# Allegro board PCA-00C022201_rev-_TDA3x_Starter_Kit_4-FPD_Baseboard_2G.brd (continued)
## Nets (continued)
DGND: C2.2 C3.2 C5.2 C6.2 C7.2 C20.2 C21.2 C23.2 C24.2 C25.1 C26.2 C27.2 C28.2 C29.1 C30.2 C31.2 C32.2 C33.1 C34.1 C35.2 C36.2 C37.2 C38.1 C39.1 C40.1 C41.2 C42.2 C43.2 C44.1 C45.1 C46.2 C47.2 C48.2 C49.1 C50.1 C51.1 C52.2 C53.2 C54.2 C55.1 C56.1 C57.2 C58.2 C59.2 C60.1 C63.2 C65.1 C66.2 C67.1 C68.2 C69.1 C70.2 C71.1 C72.2 C79.1 C80.2 C81.1 C82.2 C83.1 C84.2 C85.1 C86.2 C107.2 C108.2 C109.2 C110.2 C111.2 C123.2 C124.2 C125.2 C126.2 C127.2 C128.2 C129.2 C130.2 C131.2 C132.2 C135.2 C136.2 C137.2 C140.2 C141.2 C142.2 C143.2 C144.2 C145.2 C146.2 C150.2 C151.2 C152.2 C153.2 C155.1 C156.2 C157.2 C158.2 C159.2 C160.2 C161.2 C162.2 C163.2 C164.2 C165.2 C166.2 C167.2 C168.2 C175.2 C176.2 C177.2 C178.2 C179.2 C180.2 C181.2 C182.2 C183.2 C184.2 C186.2 C187.2 C191.2 C192.2 C193.2 C194.2 C207.2 C208.2 C213.2 C217.2 C218.2 C220.2 C221.2 C222.2 C223.2 C224.2 C229.2 C230.2 C231.2 C232.2 C235.2 C236.2 C237.2 C238.2 C239.2 C240.2 C241.2 C242.2 C243.2 C246.2 C247.2 C248.2 C250.2 C251.2 C252.2 C253.2 C254.2 C255.2 C256.2 C257.2 C258.2 C259.2 C260.2 C261.2 C262.2 C263.2 C264.2 C265.2 C266.2 C267.2 D1.A1 D1.A2 D8.1 D9.2 D21.A D23.C(CATHODE) J6.1 J6.2 J6.3 J6.4 J7.1 J7.2 J7.3 J7.4 J8.1 J8.2 J8.3 J8.4 J9.1 J9.2 J9.3 J9.4 J13.16 J13.57 J13.58 J13.61 J13.62 J13.63 J13.64(GND4) J14.93 J14.94 J14.99 J14.100 J14.105 J14.106 J14.111 J14.181 J14.182 J14.183 J14.184 J14.185 J14.186 J14.187 J14.188 J14.189(GND9) J14.190 J14.191 J14.192 J19.1 J19.4 J19.7 J19.10 J19.13 J19.20 J19.21 J19.22 J19.23 J21.6(VSS) J21.10 J25.2 J25.3 J26.1 J26.4 J26.7 J26.10 J26.13 J26.20 J26.21 J26.22 J26.23 J27.15 J27.16 J28.5 J28.7 J29.3 L41.1 Q7.2(S) Q8.2(S) R13.2 R14.2 R28.2 R31.2 R35.2 R53.2 R61.2 R67.1 R68.1 R69.1 R70.1 R75.1 R76.1 R77.1 R78.1 R111.2 R112.1 R117.2 R130.2 R135.2 R166.2 R181.2 R182.2 R183.2 R186.2 R187.2 R189.2 R191.2 R193.2 R195.2 R199.2 R201.2 R203.2 R207.2 R223.2 R224.2 R225.2 R226.2 R227.2 R228.2 R229.2 R230.2 R234.2 R238.2 R240.2 R247.2 R248.2 R269.2 R290.2 R294.2 R295.2 R296.2 R297.2 R298.2 R302.2 R303.2 R304.2 R306.1 R307.1 R315.2 R323.2 R324.2 R327.2 SW1.1 SW2.5(B4) TP2.1 TP70.1 TP72.1 U1.8 U1.11 U4.1 U4.7 U5.3 U5.6 U5.14 U5.15 U5.17 U6.65(VSS/PAD) U7.2 U9.49 U10.2 U13.1 U13.4 U13.9 U14.2 U16.16 U16.17 U16.20 U16.26 U16.32 U16.34 U16.48 U16.56 U16.64 U16.65 U20.3 U20.5 U20.8 U20.11 U20.14 U20.25(TMDS_GND.8) U20.28 U20.31 U20.34 U20.36 U21.5 U21.9 U22.12 U28.2 U38.2 U38.8 U38.9 U38.14 U38.15 U38.17 U41.2 U42.2 U43.3 U43.5 U43.8(TMDS_GND#8) U43.11 U43.14 U43.25 U43.28 U43.31 U43.34 U43.36 U44.65 U45.4 U46.8 U46.10 U46.11 U46.13 U46.14 U47.3 U47.12 U47.21 U48.10 U48.11 U48.12 U48.21 U49.4
DVDD_HDMI_IN: C239.1 C240.1 C241.1 C242.1 C243.1 L49.2 U44.24 U44.40 U44.52 U44.60
PVDD_HDMI_IN: C250.1 C251.1 L51.2 U44.57
VDD1P1: C127.1 C128.1 C129.1 C130.1 C143.1 C146.1 C255.1 C256.1 C257.1 C260.1 L37.2 U9.6 U9.24 U9.31 U9.42
VDD18_P: C47.1 C48.1 C49.2 C50.2 C51.2 L8.2 U6.1 U6.2 U6.47 U6.48
VDD18A: C27.1 C28.1 C29.2 L4.2 U6.32
VDD_1V1: C23.1 C24.1 C30.1 C41.1 C52.1 L3.2 L5.1 L7.1 L9.1 L37.1 R33.1 R34.2 TP13.1 U5.16(VOS)
VDD_1V1_EN: R172.2 TP32.1 U5.13
VDD_1V8: C184.1 J14.8 J14.10 R51.1 R58.1 TP74.1 U21.1 U21.2
VDD_2V5: C125.1 C126.1 L36.2 L38.1 R118.2 R120.1 TP17.1 U13.6(VOS)
VDD_2V5_EN: R309.2 TP33.1 U13.3
VDD_3V3: C57.1 C110.1 C160.1 C161.1 C162.1 C165.1 C167.1 C168.1 C180.1 C181.1 C182.1 C186.1 C187.1 C207.1 C217.1 C218.1 C263.1 C265.1 J13.1 J13.12 J14.7 J14.9 J21.4 J27.1 L10.1 L40.1 L42.1 L43.2 L47.1 L48.1 R107.1 R108.1 R131.2 R132.1 R133.1 R136.1 R137.1 R138.1 R152.1 R153.1 R154.1 R155.1 R156.1 R157.1 R158.1 R172.1 R184.1 R185.1 R188.1 R190.1 R192.1 R194.1 R196.1 R197.1 R200.1 R202.1 R204.1 R205.1 R206.1 R222.2 R237.1 R259.1 R260.1 R308.1 R309.1 R310.1 R312.1 R316.1 R317.1 R318.1 TP83.1 U10.5(VIO) U16.1 U16.12 U16.33 U22.24(VCC) U28.5(V+) U38.1 U38.3 U41.5(VCC) U42.5(VCC) U46.16(VCC) U48.20(VCC)
VDD_5V0: C20.1 C109.1 C175.1 C222.1 R276.1 R277.1 R313.1 R314.1 TP12.1 U4.2(VOUT) U4.3 U10.3 U20.1 U43.1
VDD_5V0_EN: R310.2 TP34.1 U4.4
VDD_BB_1V8: C26.1 C35.1 C46.1 C140.1 L4.1 L6.1 L8.1 L49.1 L50.1 L51.1 TP75.1 U14.1 U14.4(VCC) U21.7(VOUT.2) U21.8
VDD_BB_3V3: C3.1 C21.1 C124.1 C156.1 C178.1 C183.1 J14.1 J14.3 J14.5 L1.2 L2.1 R8.1 R10.1 TP1.1 U4.6 U5.10 U5.11 U5.12 U13.2 U21.4
VDD_HDMI_5V0: C166.1 J19.18 U20.38
VDD_SW_FPD: C67.2 C68.1 C71.2 C72.1 C81.2 C82.1 C85.2 C86.1 L11.2 L12.2 L21.2 L22.2 R250.1 TP11.1 U3.5 U3.6 U3.7
VDD_USB_3V3: C193.1 C194.1 C208.1 R301.1 U38.16(VCCB) U47.6
VDD_USB_5V0: C191.1 C192.1 C213.1 J23.1 U47.7 U47.8 U49.1(VCC)
VDD_VIN: C2.1 C266.1 C267.1 J25.1 R249.1 TP27.1 U1.2(VIN) U3.8 U3.9(VS#9) U3.10
VDDA1P8: U9.13 U9.48
VDDA2P5: C131.1 C132.1 C142.1 C145.1 C254.1 C262.1 L38.2 U9.3 U9.9
VDDCSI: C42.1 C43.1 C44.2 C45.2 L7.2 U6.21 U6.33
VDDFPD: C53.1 C54.1 C55.2 C56.2 L9.2 U6.52 U6.61
VDDFPD18: C36.1 C37.1 C38.2 C39.2 C40.2 L6.2 U6.49 U6.55 U6.58 U6.64
VDDIO_960: C58.1 C59.1 C60.2 C123.1 L10.2 R42.1 R59.1 R60.1 R328.1 R329.1 U6.16 U7.4(VCC)
VDDIO_HDMI_IN: C229.1 C230.1 C231.1 C232.1 C264.1 L47.2 R278.2 R280.1 R281.1 R282.1 R283.1 R286.2 R287.2 R305.1 U44.23 U44.34 U44.44 U45.8
VDDIO_PHY: C135.1 C136.1 C137.1 C141.1 C144.1 C258.1 C259.1 C261.1 L40.2 R121.1 R125.1 R311.1 U9.19 U9.30 U9.41
VDDL: C31.1 C32.1 C33.2 C34.2 L5.2 U6.13 U6.44
VIN1A_CLK0: J14.73 R271.1 TP84.1
VIN1A_D0: J14.74 RN1.4
VIN1A_D1: J14.71 RN1.3
VIN1A_D2: J14.69 RN1.2
VIN1A_D3: J14.72 RN1.1
VIN1A_D4: J14.70 RN2.4
VIN1A_D5: J14.68 RN2.3
VIN1A_D6: J14.67 RN2.2
VIN1A_D7: J14.65 RN2.1
VIN1A_D8: J14.66 RN3.4
VIN1A_D9: J14.63 RN3.3
VIN1A_D10: J14.61 RN3.2
VIN1A_D11: J14.59 RN3.1
VIN1A_D12: J14.57 RN4.4
VIN1A_D13: J14.62 RN4.3
VIN1A_D14: J14.64 RN4.2
VIN1A_D15: J14.55 RN4.1
VIN1A_DE0: J14.75 R274.1 TP86.1
VIN1A_HSYNC0: J14.78 R272.1 TP85.1
VIN1A_VSYNC0: J14.76 R273.1 TP87.1
ADC_IN2: D21.C(CATHODE) J14.20 R26.1 R231.1
ADC_IN4: J14.15 R251.2
ADC_IN5: J14.13 R252.2
ADV7611_RSTN: R290.1 U22.10 U44.56
ADV7611_SCL: R288.1 R291.2 U44.53
ADV7611_SDA: R289.1 R292.2 U44.54
BB_3V3_PG: J14.130 R8.2 TP28.1 TP56.1 U1.10
BOARD_ID0: R185.2 R186.1 U22.13
BOARD_ID1: R187.1 R188.2 U22.14
BOARD_ID2: R189.1 R190.2 U22.15
BOARD_ID3: R191.1 R192.2 U22.16
BUF_INPUT0: J28.2 R265.1
BUF_INPUT1: J28.4 R266.1
BUF_OUT0: J28.6 R267.1
BUF_OUT1: J28.8 R268.1
CSI2_0_DX0: J14.104 U6.23
CSI2_0_DX1: J14.109 U6.25
CSI2_0_DX2: J14.103 U6.27
CSI2_0_DX3: J14.98 U6.29
CSI2_0_DX4: J14.97 U6.31
CSI2_0_DY0: J14.102 U6.22
CSI2_0_DY1: J14.107 U6.24
CSI2_0_DY2: J14.101 U6.26
CSI2_0_DY3: J14.96 U6.28
CSI2_0_DY4: J14.95 U6.30
CVDD_HDMI_IN: C246.1 C247.1 C248.1 L50.2 U44.2 U44.14
DCAN1_H: C107.1 D9.1 J28.1 R92.1 U10.7
DCAN1_L: C108.1 D8.2 J28.3 R93.1 U10.6
DCAN1_RX: J14.113 R91.1
DCAN1_STSB: R89.1 U22.11
DCAN1_TX: J14.115 R90.1
DCAN2_RX: J14.110 J27.14
DCAN2_TX: J14.108 J27.12
EDID_EEPROM_WP: R305.2 SW2.4 U45.7(WP)
EDID_SCL: TP88.1 U45.6 U46.4
EDID_SDA: TP89.1 U45.5 U46.7
EDID_SEL: R307.2 SW2.3 U46.1
EMU0: J13.19 J14.175
EMU1: J13.21 J14.173
EMU_RSTN: J13.6 J14.172 R108.2
ENET_CLKIN: R233.2 U9.15
FPD_960_EN: R270.1 U22.17
FPD_960_GPIO4: TP22.1 U6.17 U22.4
FPD_960_GPIO5: TP24.1 U6.18 U22.5
FPD_960_GPIO6: TP23.1 U6.19 U22.6
FPD_960_GPIO7: TP25.1 U6.20 U22.7
FPD_960_IDX: C63.1 R51.2 R53.1 U6.46
FPD_960_MODE: R58.2 R61.1 U6.45
FPD_960_PDB: R269.1 R270.2 U6.3
FPD_960_REFCLK: R45.1 U7.3
FPD_960_SCL: R38.1 R39.1 U6.12
FPD_960_SCL2: J29.1 R43.1 R44.1 R328.2 U6.8
FPD_960_SDA: R36.1 R37.1 U6.11
FPD_960_SDA2: J29.2 R40.1 R41.1 R329.2 U6.7
FPD_960_TESTEN: R60.2 SW1.2(B1) U6.4
GPIO2_0: J14.77 R231.2
GPIO2_19: J14.56 R180.1 R234.1 TP40.1
GPIO3_19: J14.89 U41.6
GPIO3_20: J14.81 U41.4
GPIO3_21: J14.85 R297.1 U42.1
GPIO3_22: J14.87 R298.1 U42.3
GPIO3_23: J14.83 R24.1
GPIO3_24: J14.79 R25.1
GPIO4_5: J14.161 TP18.1 U6.9
GPIO4_6: J14.163 TP19.1 U6.10
GPIO4_7: J14.165 TP20.1 U6.14
GPIO4_8: J14.167 TP21.1 U6.15
GPIO4_21: J14.58 R287.1 U44.55
GPIO4_22: J14.60 R197.2 U22.1
GPMC_AD3: J14.144 SW2.2
GPMC_AD4: J14.145 SW2.1
GPMC_AD10: J14.151 R202.2
GPMC_AD11: J14.152 R201.1
GPMC_AD12: J14.153 R200.2
GPMC_CS1: J14.125 TP58.1
GPMC_CS2: J14.127 TP61.1
GPMC_CS3: J14.133 TP63.1
GPMC_CS4: J14.131 TP60.1
GPMC_CS5: J14.129 TP62.1
GPMC_CS6: J14.123 TP59.1
HDMI_IN_5V0: C220.1 J26.18 R275.1 R285.2
HDMI_IN_CEC: R283.2 U43.16 U44.61
HDMI_IN_CLK: R271.2 U44.25
HDMI_IN_CLKN: J26.12 U43.15 U43.24 U44.3
HDMI_IN_CLKP: J26.11 U43.13 U43.26 U44.4
HDMI_IN_D0: RN1.5 U44.43
HDMI_IN_D0N: J26.9 U43.12 U43.27 U44.6
HDMI_IN_D0P: J26.8 U43.10 U43.29 U44.7
HDMI_IN_D1: RN1.6 U44.42
HDMI_IN_D1N: J26.6 U43.9 U43.30 U44.9
HDMI_IN_D1P: J26.5 U43.7 U43.32 U44.10
HDMI_IN_D2: RN1.7 U44.41
HDMI_IN_D2N: J26.3 U43.6 U43.33 U44.12
HDMI_IN_D2P: J26.2 U43.4 U43.35 U44.13
HDMI_IN_D3: RN1.8 U44.39
HDMI_IN_D4: RN2.5 U44.38
HDMI_IN_D5: RN2.6 U44.37
HDMI_IN_D6: RN2.7 U44.36
HDMI_IN_D7: RN2.8 U44.35
HDMI_IN_D8: RN3.5 U44.33
HDMI_IN_D9: RN3.6 U44.32
HDMI_IN_D10: RN3.7 U44.31
HDMI_IN_D11: RN3.8 U44.30
HDMI_IN_D12: RN4.5 U44.29
HDMI_IN_D13: RN4.6 U44.28
HDMI_IN_D14: RN4.7 U44.27
HDMI_IN_D15: RN4.8 U44.26
HDMI_IN_DDC_SCL: R281.2 U43.17 U44.62 U46.2
HDMI_IN_DDC_SDA: R282.2 U43.18 U44.63 U46.5
HDMI_IN_DE: R274.2 U44.45
HDMI_IN_HPDET: R286.1 U43.19 U44.1
HDMI_IN_HS: R272.2 U44.46
HDMI_IN_VS: R273.2 U44.47
HDMI_OUT_HPD: R316.2 U20.19 U22.19
HDMI_OUT_SCL: R318.2 R319.2 R320.2 U20.17
HDMI_OUT_SDA: R317.2 R321.2 R322.2 U20.18
I2C1_SCL: J14.156 J27.7 R38.2 R43.2 R291.1 R319.1
I2C1_SDA: J14.154 J27.9 R36.2 R40.2 R292.1 R321.1
I2C2_SCL: J14.120 J27.11 R39.2 R44.2 R288.2 R320.1 U22.22 U28.1 U46.3
I2C2_SDA: J14.122 J27.13 R37.2 R41.2 R289.2 R322.1 U22.23 U28.6 U46.6
LPTX_C_N: C62.2 R46.2 TP6.1
LPTX_C_P: C61.2 R46.1 TP5.1
LPTXN: C62.1 U6.57
LPTXP: C61.1 U6.56
MDIO_D: J14.91 R125.2 R311.2 TP47.1 U9.17
MDIO_MCLK: J14.92 TP48.1 U9.16
MMC_CLK: J21.5 R148.2 R155.2
MMC_CMD: J21.3 R147.2 R154.2
MMC_DAT0: J21.7 R149.2 R156.2
MMC_DAT1: J21.8 R150.2 R157.2
MMC_DAT2: J21.1 R145.2 R152.2
MMC_DAT3: J21.2 R146.2 R153.2
NTRST: J13.9 R107.2 R110.1
PB_RESETN: J14.171 TP77.1
PG_1V1: R34.1 TP69.1 U5.4
PHY_LED0: D12.A U9.47
PHY_LED1: J24.15 U9.46
PHY_LED2: J24.14 U9.45
PMIC_REGEN_3V3: J14.26 TP80.1
PWRON: J14.24 TP79.1
QSPI1_RTCLK: J14.121 TP57.1
RGMII0_RXC: J14.90 R148.1
RGMII0_RXCTL: J14.82 R147.1
RGMII0_RXD0: J14.86 R146.1
RGMII0_RXD1: J14.80 R145.1
RGMII0_RXD2: J14.84 R150.1
RGMII0_RXD3: J14.88 R149.1
RGMII1_RXC: J14.155 R199.1 U48.2
RGMII1_RXCTL: J14.132 U48.7
RGMII1_RXD0: J14.143 R205.2 U48.3
RGMII1_RXD1: J14.142 R206.2 U48.4
RGMII1_RXD2: J14.141 R207.1 U48.5
RGMII1_RXD3: J14.140 U48.6
RGMII1_TXC: J14.135 U9.29
RGMII1_TXCTL: J14.138 U9.37
RGMII1_TXD0: J14.134 U9.28
RGMII1_TXD1: J14.136 U9.27
RGMII1_TXD2: J14.137 U9.26
RGMII1_TXD3: J14.139 U9.25
RIN0_C_N: C75.1 C77.2 L19.1 L19.2 R67.2
RIN0_C_P: C73.1 J6.5 L17.2 L19.3 L19.4
RIN0_N: C75.2 U6.51
RIN0_P: C73.2 U6.50
RIN1_C_N: C76.1 C78.2 L20.1 L20.2 R68.2
RIN1_C_P: C74.1 J7.5 L18.2 L20.3 L20.4
RIN1_N: C76.2 U6.54
RIN1_P: C74.2 U6.53
RIN2_C_N: C89.1 C91.2 L29.1 L29.2 R75.2
RIN2_C_P: C87.1 J8.5 L27.2 L29.3 L29.4
RIN2_N: C89.2 U6.60
RIN2_P: C87.2 U6.59
RIN3_C_N: C90.1 C92.2 L30.1 L30.2 R76.2
RIN3_C_P: C88.1 J9.5 L28.2 L30.3 L30.4
RIN3_N: C90.2 U6.63
RIN3_P: C88.2 U6.62
RSTOUTN: J14.170 TP78.1 U22.3
RTCK: J13.7 J14.179
RX_CLK: R179.2 U9.32
RX_CTRL: R174.2 U9.38
RX_D0: RN5.8 U9.33
RX_D1: RN5.7 U9.34
RX_D2: RN5.6 U9.35
RX_D3: RN5.5 U9.36
SD_DETECT: R151.2 R158.2 U22.18
SPI1_CS1/SPI3_CS1: J14.162 J27.10
SW_RX_CLK: R179.1 U48.18
SW_RX_CTRL: R174.1 U48.13
SW_RX_D0: RN5.1 U48.17
SW_RX_D1: RN5.2 U48.16
SW_RX_D2: RN5.3 U48.15
SW_RX_D3: RN5.4 U48.14
TCLK: J13.3 J14.180
TD_A_N: J24.10 U9.2
TD_A_P: J24.11 U9.1
TD_B_N: J24.5 U9.5
TD_B_P: J24.4 U9.4
TD_C_N: J24.2 U9.8
TD_C_P: J24.3 U9.7
TD_D_N: J24.9 U9.11
TD_D_P: J24.8 U9.10
TDI: J13.5 J14.174
TDO: J13.4 J14.176
TFP410_DKEN: R137.2 U16.35
TFP410_HTPLG: R136.2 U16.9
TFP410_MSEN: R138.2 U16.11
TFP410_PDN: R134.2 U22.20
TFP410_TFADJ: R139.1 U16.19
TMS: J13.2 J14.178
TRSTN: J14.177 R109.2 R110.2
TRSTPD: J13.8 R109.1 R111.1
TVDD: C157.1 C158.1 C163.1 L42.2 R139.2 U16.23 U16.29
TVDD_HDMI_IN: C235.1 C236.1 C237.1 C238.1 L48.2 U44.5 U44.8 U44.11
TXC_N: J19.12 U16.21 U20.15 U20.24
TXC_P: J19.11 U16.22 U20.13 U20.26
TXD0_N: J19.9 U16.24 U20.12 U20.27
TXD0_P: J19.8 U16.25 U20.10 U20.29
TXD1_N: J19.6 U16.27 U20.9 U20.30
TXD1_P: J19.5 U16.28 U20.7 U20.32
TXD2_N: J19.3 U16.30 U20.6 U20.33
TXD2_P: J19.2 U16.31 U20.4 U20.35
UART1_RXD/DCAN2_TX: J14.117 J27.3
UART1_TXD/DCAN2_RX: J14.119 J27.5
UART2_CTSN: J14.114 J27.6 Q7.1 R324.1
UART2_RTSN: J14.112 J27.8 Q8.1 R323.1
UART2_RXD: J14.118 J27.4
UART2_TXD: J14.116 J27.2
UART3_CTSN: J14.164 R104.2
UART3_RTSN: J14.166 R101.2
UART3_RXD_BOOT: J14.158 R105.2
UART3_TXD_BOOT: J14.160 R102.2
USB_CTS: R299.1 U47.15
USB_DM: J23.2 U47.5 U49.2 U49.5
USB_DP: J23.3 U47.4 U49.3
USB_RTS: R300.1 U47.16
USB_RXD: U38.11 U47.17
USB_TXD: U38.13 U47.18
VOUT1_CLK: J14.51 U16.57
VOUT1_D0: J14.43 U16.63
VOUT1_D1: J14.41 U16.62
VOUT1_D2: J14.39 U16.61
VOUT1_D3: J14.37 U16.60
VOUT1_D4: J14.54 U16.59
VOUT1_D5: J14.52 U16.58
VOUT1_D6: J13.13 J14.35 U16.55
VOUT1_D7: J13.17 J14.50 U16.54
VOUT1_D8: J13.23 J14.48 U16.53
VOUT1_D9: J13.25 J14.46 U16.52
VOUT1_D10: J13.27 J14.44 U16.51
VOUT1_D11: J13.29 J14.42 U16.50
VOUT1_D12: J13.31 J14.40 U16.47
VOUT1_D13: J13.33 J14.38 U16.46
VOUT1_D14: J13.35 J14.36 U16.45
VOUT1_D15: J13.37 J14.34 U16.44
VOUT1_D16: J13.39 J14.31 U16.43
VOUT1_D17: J13.41 J14.32 U16.42
VOUT1_D18: J13.43 J14.33 U16.41
VOUT1_D19: J13.45 J14.30 U16.40
VOUT1_D20: J13.47 J14.29 U16.39
VOUT1_D21: J13.49 J14.27 U16.38
VOUT1_D22: J13.51 J14.28 U16.37
VOUT1_D23: J13.53 J14.25 U16.36
VOUT1_DE: J14.45 U16.2
VOUT1_FLD: J14.53 R237.2 U48.19
VOUT1_HSYNC: J14.49 U16.4
VOUT1_VSYNC: J14.47 U16.5(VSYNC)
WARM_RESETN: J14.169 TP76.1
XREF_CLK/TIMER3: J14.124 R121.2 TP14.1 U9.44
N16778655: C1.1 U1.1
N16778658: C1.2 D1.C(CATHODE) L1.1 U1.9
N16779093: C6.1 R12.1 U1.7
N16779143: R13.1 U1.5
N16779358: C5.1 U1.4
N16782242: L2.2 U4.5
N16784059: R26.2 R28.1 U3.14
N16784098: R24.2 U3.3
N16784610: R30.1 U3.13
N16784791: D23.A1 D23.A2 R30.2 R31.1 U3.2 U3.15
N16787891: L3.1 U5.1 U5.2
N16788418: C25.2 U5.9
N16788506: C22.2 U5.7
N16788509: C22.1 U5.8
N16799359: C77.1 R69.2
N16799482: L13.1 LR5.1 R63.1
N16799508: L13.2 L14.1 R63.2 R64.1
N16799567: C65.2 C66.1 L11.1 L14.2 R64.2
N16800770: C78.1 R70.2
N16800832: L15.1 LR6.1 R65.1
N16800854: L15.2 L16.1 R65.2 R66.1
N16800876: C69.2 C70.1 L12.1 L16.2 R66.2
N16801557: C91.1 R77.2
N16801619: L23.1 LR7.1 R71.1
N16801641: L23.2 L24.1 R71.2 R72.1
N16801663: C79.2 C80.1 L21.1 L24.2 R72.2
N16802378: C92.1 R78.2
N16802440: L25.1 LR8.1 R73.1
N16802462: L25.2 L26.1 R73.2 R74.1
N16802472: C83.2 C84.1 L22.1 L26.2 R74.2
N16805253: R59.2 U7.1
N16808896: R45.2 U6.5
N16808937: R42.2 TP4.1 U6.6
N16828608: R90.2 U10.1
N16828611: R91.2 U10.4
N16829078: C111.1 R92.2 R93.2
N16848362: J13.15 R112.2
N16871816: R117.1 U9.12
N16872761: L36.1 U13.7
N16872796: R118.1 U13.8
N16872856: R119.1 R120.2 U13.5
N16877045: R233.1 U14.3
N16921638: R25.2 U3.12
N16945191: C150.1 J24.12
N16950158: C151.1 J24.6
N16950163: C152.1 J24.1
N16950168: C153.1 J24.7
N16959967: R131.1 U16.3
N16959972: R130.1 R134.1 U16.10
N16959998: R132.2 U16.15
N16960003: R133.2 U16.14
N16960049: R135.1 U16.13
N16962010: C159.1 C164.1 L43.1 U16.18
N16974466: J21.9 R151.1
N16989017: R89.2 R166.1 U10.8
N17023402: R10.2 R14.1 U1.6
N17041661: R180.2 U9.43
N17043205: D12.C(CATHODE) R181.1
N17043208: J24.13 R182.1
N17043211: J24.16 R183.1
N17061008: R184.2 TP44.1 U21.3
N17061570: C179.1 U21.6
N17062531: R193.1 R194.2 U22.2
N17062635: R195.1 R196.2 U22.21
N17083264: R222.1 U28.4
N17084179: J14.11 TP50.1
N17084298: J14.23 TP51.1
N17084336: J14.12 TP52.1
N17084566: J14.22 TP53.1
N17086992: J14.126 TP54.1
N17087001: J14.128 TP55.1
N17088234: MH1.1 R223.1
N17088237: MH2.1 R224.1
N17088240: MH3.1 R225.1
N17088243: MH4.1 R226.1
N17088661: MH5.1 R227.1
N17088663: MH6.1 R228.1
N17088675: MH7.1 R229.1
N17088677: MH8.1 R230.1
N17350751: J23.5 J23.6 J23.7 J23.8 J23.9(SHIELD4) R240.1
N17371221: R102.1 U38.6
N17371356: R105.1 U38.4
N17389734: R247.1 R249.2 R251.1
N17389895: R248.1 R250.2 R252.1
N17515572: D18.C(CATHODE) Q7.3
N17515594: D18.A R259.2
N17515834: D17.C(CATHODE) Q8.3
N17515881: D17.A R260.2
N17688900: R204.2 SW2.7
N17688914: R203.1 SW2.8
N17750408: L17.1 LR1.2
N17835449: C155.2 J24.17 J24.18(SHLD2) L41.2
N17854884: C177.1 R312.2 U20.2
N17856030: C176.1 U20.37
N17857226: J19.15 R313.2 U20.22
N17857229: J19.16(SDA) R314.2 U20.21
N17857232: J19.19 R315.1 U20.20
N17858343: J26.14 R278.1 U43.23
N17858344: J26.15 R277.2 U43.22
N17858345: J26.16(SDA) R276.2 U43.21
N17858346: J26.19 R275.2 R294.1 U43.20
N17880680: C221.1 U43.37
N17880809: C223.1 R280.2 U43.2
N17882114: C224.1 R285.1 U44.64
N17895085: C252.1 R293.1 U44.58(XTALP) Y2.1
N17895092: C253.1 R293.2 U44.59 Y2.2
N17937761: R238.1 U48.1
N17941586: R265.2 R296.1 U41.1
N17941618: R266.2 R295.1 U41.3
N17941727: R267.2 U42.6
N17941759: R268.2 U42.4
N17942689: R299.2 U38.10
N17942746: R300.2 U38.12
N17942762: R104.1 U38.5
N17942771: R101.1 U38.7
N17945605: R301.2 U47.9
N17947242: L27.1 LR3.2
N17947474: L28.1 LR4.2
N17947670: L18.1 LR2.2
N17947891: LR1.1 LR5.2
N17947954: LR2.1 LR6.2
N17948346: LR4.1 LR8.2
N17948389: LR3.1 LR7.2
N17949147: R304.1 U45.1
N17949152: R303.1 U45.2
N17949167: R302.1 U45.3
N17955828: R306.2 U46.15
N17957422: R308.2 SW2.6
N18040269: R12.2 R325.1
N18040280: C7.1 R325.2
N18040766: R35.1 R326.2 U5.5
N18041733: R119.2 R327.1
N167880061: R33.2 R326.1

Pads without a net: D8 3; D9 3; J13 10 11 14 18 20 22 24 26 28 30 32 34 36 38 40 42 44 46 48 50 52 54 55 56 59 60; J14 2 4 6 14 16 17 18 19 21 146 147 148 149 150 157 159 168; J19 14 17; J23 4; J26 17; U1 3; U3 1 4 11; U6 34 35 36 37 38 39 40 41 42 43; U9 14 18 20 21 22 23 39 40; U16 6 7 8 49; U20 16 23; U22 8 9; U28 3; U43 38; U44 15 16 17 18 19 20 21 22 48 49 50 51; U46 9 12; U47 1 2 10 11 13 14 19 20; U48 8 9

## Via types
v1: diameter 0.457, hole 0.203, TOP to BOTTOM, 903 vias
v2: diameter 0.559, hole 0.305, TOP to BOTTOM, 201 vias

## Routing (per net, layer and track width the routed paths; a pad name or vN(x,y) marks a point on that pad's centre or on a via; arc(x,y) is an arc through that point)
DGND: length 1055.8
  TOP w0.203: v1(94.52,4.67) 94.81,4.96 U5.3 ; U45.4 v1(67.99,64.23) ; U48.12 v1(83.54,20.83) ; U48.11 v1(84.84,19.04) ; R247.2 v1(28.02,60.48) ; J21.6 v2(82.89,69.04)
  TOP w0.229: J19.7 v1(120.9,54.41) ; J26.7 v1(55.75,63.75) ; J26.13 v1(58.15,63.75) ; J19.13 v1(120.9,52.01) ; J19.4 v1(120.9,55.61) ; J19.1 v1(120.9,56.81) ; J26.10 v1(56.95,63.75) ; J26.4 v1(54.55,63.75) ; J19.10 v1(120.9,53.21) ; J26.1 v1(53.35,63.75)
  TOP w0.254: v1(65.07,12.8) 65.56,12.8 66.52,11.84 v1(66.52,10.86) ; v1(62.02,8.7) J14.93 62.02,11.6 63.22,12.8 v1(63.53,12.8)
  TOP w0.279: U20.8 v1(110.87,55.16) ; U43.5 v1(53.5,53.85) ; U43.28 v1(56.5,57.66) ; U20.5 v1(110.87,56.66) ; U20.28 v1(114.68,53.66) ; U43.14 v1(58,53.85) ; U43.3 v1(52.5,53.85) ; U20.36 v1(114.3,57.66) ; U20.25 v1(114.68,52.16) ; U20.31 v1(114.68,55.16) ; U43.11 v1(56.5,53.85) ; U43.8 v1(55,53.85) ; U20.14 v1(110.87,52.16) ; U20.11 v1(110.87,53.66) ; U20.34 v1(114.68,56.66) ; U20.3 v1(111.12,57.66) ; U43.25 v1(58,57.66) ; U43.36 v1(52.5,57.66) ; U43.31 v1(55,57.66) ; U43.34 v1(53.5,57.66)
  TOP w0.292: J14.100 v1(63.52,4.7) ; J14.99 v1(63.52,10.86) ; J14.105 v1(65.02,10.86) ; J14.111 v1(66.52,10.86) ; U16.48 93.75,57.89 v1(93.22,58.42) ; v1(38.43,13.03) 38.43,13.58 ; J14.106 v1(65.02,4.7)
  TOP w0.305: v1(62.02,4.7) J14.94 ; 103.25,47.68 101.29,47.68 101.25,47.72 ; 101.25,47.72 v1(101.09,47.88) ; 101.25,47.72 U16.16 ; U47.3 v1(32.63,59.56) ; v1(93.98,47.88) 93.78,47.68 U16.64 ; v1(101.09,49.66) 101.09,49.49 101.4,49.18 103.25,49.18 ; v1(93.98,51.44) 93.73,51.68 U16.56 ; 103.25,52.18 101.4,52.18 101.09,51.88 v1(101.09,51.44) ; U47.12 v1(31.63,54.74) ; U16.48 93.75,55.22 v1(93.98,54.99) ; U41.2 v1(124.78,61.09) ; v1(71.2,68.28) R304.2 R303.2 R302.2 v1(67.39,68.28) ; U16.34 100.75,55.33 v1(101.09,54.99) 101.28,55.18 103.25,55.18
  TOP w0.381: D9.2 v1(112.01,68.39) ; C47.2 v1(33.1,26.11) ; C179.2 39.73,12.75 v1(39.73,12.34) ; R187.2 14.16,7.05 13.46,6.35 v1(13.46,5.97) ; v2(19.51,6.83) 19.51,7.61 R191.2 ; R269.2 v1(28.7,36.83) ; R135.2 v1(101.47,43.37) ; C33.1 C32.2 34.34,23.06 v1(34.59,23.32) ; C45.1 35.03,22.12 v1(34.54,22.61) ; C252.2 v1(64.77,42.67) ; C54.2 26.01,26.49 25.83,26.31 v1(25.82,26.31) ; R111.2 60.89,30.24 v1(60.89,30.63) ; v1(31.58,32.44) C49.1 C48.2 ; v1(25.77,27.75) 25.91,27.61 C56.1 ; R189.2 16.83,6.79 v1(17.65,5.97) ; C53.2 v1(25.82,22) ; v1(72.01,53.38) 71.29,53.38 R306.1 ; D8.1 v1(112.01,62.8) ; C43.2 v1(34.82,27.1) ; v1(34.54,49.34) 35.3,49.34 C208.2 35.43,49.46 v1(35.43,48.7) 35.43,47.94 C207.2 35.3,48.07 v1(34.54,48.07) ; R238.2 v1(76.58,17.54) ; v1(25.77,29.11) C36.2 ; v1(28.85,32.45) 28.12,32.45 C35.2 28.38,31.7 v1(28.85,31.7) ; C31.2 v1(34.24,28.12) ; U14.2 v1(95.36,41.54) ; R234.2 v1(85.85,27.05) ; C178.2 v1(37.91,12.5) ; C42.2 v1(34.8,23.93) ; U22.12 v2(26.89,9.93) ; C265.2 v1(69.47,52.07) ; C107.2 v1(104.14,68.07) ; v1(119.57,60.07) C218.2 ; C34.1 v1(35.94,28.12) ; v1(32.37,37.85) 32.07,38.16 C123.2 ; D21.A 24.19,58.99 v1(24.2,58.99) ; R307.1 v1(67.5,51.44) ; v1(45.47,66.42) C263.2 v1(45.47,67.94) ; R294.2 v1(62.42,60.22) ; C39.1 v1(31.06,24.59) ; C44.1 v1(34.8,25.98) ; C253.2 v1(64.77,45.72) ; C55.1 v1(25.82,23.11) ; R248.2 v1(6.67,61.4) ; C37.2 30.2,28.78 v1(30.99,27.99) ; v1(11.49,5.97) R186.2 ; C181.2 v1(40.2,41.4) ; C40.1 v1(31.04,26.09) ; C108.2 v1(104.14,63.12) ; C38.1 v1(30.89,22.61) ; U10.2 v1(98.3,66.23) ; SW2.5 v1(7.62,5.71)
  TOP w0.508: SW1.1 v2(20.65,25.25) ; v1(28.88,19.96) 28.78,20.07 C50.1 ; v1(32.82,6.73) v1(37.64,6.73) J14.182 v1(39.8,6.73) J14.183 J14.184 v2(51.27,6.73) J14.185 J14.186 v2(61.68,6.73) v1(63.49,6.73) J14.187 v1(65.01,6.73) v2(67.63,6.73) J14.188 J14.189 v2(74.93,6.73) J14.190 v2(81.53,6.73) J14.191 v2(87.25,6.73) J14.192 v2(91.44,6.73) ; v1(24.46,16.28) 25.25,17.07 ; 25.25,17.07 v1(25.25,16.28) ; 25.25,17.07 C52.2 ; v1(31.36,18.35) 32.35,18.35 C30.2 33.12,18.47 v1(33.12,17.02) ; J21.10 v2(88.14,65.57)
  GND1 w0.254: 41.35,49.4 J27.15 ; J27.15 42.42,48.34 ; J27.15 43.49,49.4 ; J27.15 42.42,50.47 ; 123.28,10.57 J25.2 ; J25.2 124.1,12.5 ; J25.2 123.28,14.43 ; J25.2 122.45,12.5 ; 119.92,58.64 J19.20 ; J19.20 121.04,57.86 ; J19.20 122.17,58.64 ; J19.20 121.04,59.42 ; J6.3 3.69,12.88 ; J6.3 2.31,11.5 ; J6.3 2.31,14.25 ; J6.3 0.93,12.88 ; 9.31,42.9 J8.1 ; J8.1 10.69,44.27 ; J8.1 9.31,45.65 ; J8.1 7.93,44.27 ; J6.1 10.69,18.87 ; J6.1 9.31,17.5 ; J6.1 9.31,20.25 ; J6.1 7.93,18.87 ; J9.4 2.31,58.35 ; J9.4 2.31,55.6 ; J9.4 0.93,56.97 ; J9.4 3.69,56.97 ; J19.22 125.54,59.42 ; J19.22 125.54,57.86 ; J19.22 124.52,58.64 ; J27.16 40.95,49.4 ; J27.16 39.88,50.47 ; J27.16 39.88,48.34 ; J27.16 38.81,49.4 ; TP70.1 115.09,3.81 ; TP70.1 113.67,2.38 ; TP70.1 112.24,3.81 ; TP70.1 113.67,5.24 ; 114.3,61.81 J28.7 113.62,62.48 ; J7.2 10.69,25.58 ; J7.2 9.31,24.2 ; J7.2 9.31,26.95 ; J7.2 7.93,25.58 ; J26.20 51.52,65.02 ; J26.20 50.75,63.89 ; J26.20 52.3,63.89 ; J26.20 51.52,62.77 ; 61.6,68.39 J26.23 ; J26.23 62.37,67.37 ; J26.23 63.15,68.39 ; J8.3 3.69,38.28 ; J8.3 2.31,36.9 ; J8.3 2.31,39.65 ; J8.3 0.93,38.28 ; TP2.1 26.06,34.86 ; TP2.1 25.04,34.86 ; TP2.1 25.55,34.35 ; TP2.1 25.55,35.37 ; J6.4 2.31,20.25 ; J6.4 3.69,18.87 ; J6.4 0.93,18.87 ; J6.4 2.31,17.5 ; J26.21 63.15,63.89 ; J26.21 61.6,63.89 ; J26.21 62.37,62.77 ; J26.21 62.37,65.02 ; 120.47,16.47 J25.3 ; J25.3 122.4,17.3 ; J25.3 118.55,17.3 ; J25.3 120.47,18.13 ; 121.04,47.01 J19.21 ; J19.21 121.04,48.57 ; J19.21 119.92,47.79 ; J19.21 122.17,47.79 ; J9.2 10.69,50.98 ; J9.2 9.31,49.6 ; J9.2 7.93,50.98 ; J9.2 9.31,52.35 ; TP72.1 1.91,9.49 ; TP72.1 3.33,8.06 ; TP72.1 1.91,6.64 ; J7.1 9.31,32.95 ; J7.1 7.93,31.57 ; J7.1 10.69,31.57 ; J7.1 9.31,30.2 ; J29.3 31.37,42.47 ; J29.3 32.44,41.4 ; J29.3 31.37,40.33 ; J29.3 30.3,41.4 ; J8.4 2.31,45.65 ; J8.4 2.31,42.9 ; J8.4 0.93,44.27 ; J8.4 3.69,44.27 ; 50.75,68.39 J26.22 ; J26.22 51.52,67.37 ; J26.22 52.3,68.39 ; 125.54,47.01 J19.23 ; J19.23 125.54,48.57 ; J19.23 124.52,47.79 ; J7.4 3.69,31.57 ; J7.4 0.93,31.57 ; J7.4 2.31,30.2 ; J7.4 2.31,32.95 ; 113.62,63.75 J28.5 113.77,63.22 ; 2.31,24.2 J7.3 ; J7.3 2.31,26.95 ; J7.3 3.69,25.58 ; J7.3 0.93,25.58 ; J6.2 9.31,14.25 ; J6.2 9.31,11.5 ; J6.2 7.93,12.88 ; J6.2 10.69,12.88 ; J9.1 10.69,56.97 ; J9.1 9.31,58.35 ; J9.1 7.93,56.97 ; J9.1 9.31,55.6 ; 2.31,49.6 J9.3 ; J9.3 0.93,50.98 ; J9.3 3.69,50.98 ; J9.3 2.31,52.35 ; 9.31,36.9 J8.2 ; J8.2 9.31,39.65 ; J8.2 7.93,38.28 ; J8.2 10.69,38.28
  GND2 w0.254: J25.2 123.28,14.43 ; J25.2 123.28,10.57 ; J25.2 122.45,12.5 ; J25.2 124.1,12.5 ; 7.93,12.88 J6.2 ; J6.2 9.31,11.5 ; J6.2 9.31,14.25 ; J6.2 10.69,12.88 ; J19.21 121.04,48.57 ; J19.21 119.92,47.79 ; J19.21 121.04,47.01 ; J19.21 122.17,47.79 ; J7.1 9.31,32.95 ; J7.1 7.93,31.57 ; J7.1 10.69,31.57 ; J7.1 9.31,30.2 ; 118.55,17.3 J25.3 ; J25.3 120.47,18.13 ; J25.3 122.4,17.3 ; J25.3 120.47,16.47 ; J9.4 2.31,58.35 ; J9.4 2.31,55.6 ; J9.4 0.93,56.97 ; J9.4 3.69,56.97 ; 7.93,38.28 J8.2 ; J8.2 9.31,36.9 ; J8.2 9.31,39.65 ; J8.2 10.69,38.28 ; 2.31,36.9 J8.3 ; J8.3 3.69,38.28 ; J8.3 2.31,39.65 ; J8.3 0.93,38.28 ; J9.1 10.69,56.97 ; J9.1 7.93,56.97 ; J9.1 9.31,58.35 ; J9.1 9.31,55.6 ; 2.31,11.5 J6.3 ; J6.3 3.69,12.88 ; J6.3 2.31,14.25 ; J6.3 0.93,12.88 ; J7.3 2.31,26.95 ; J7.3 3.69,25.58 ; J7.3 0.93,25.58 ; J7.3 2.31,24.2 ; 39.88,48.34 J27.16 ; J27.16 40.95,49.4 ; J27.16 39.88,50.47 ; J27.16 38.81,49.4 ; TP72.1 1.91,9.49 ; TP72.1 3.33,8.06 ; TP72.1 1.91,6.64 ; J19.22 125.54,59.42 ; J19.22 125.54,57.86 ; J19.22 124.52,58.64 ; 113.77,63.22 J28.5 113.62,63.75 ; J26.23 63.15,68.39 ; J26.23 62.37,67.37 ; J26.23 61.6,68.39 ; 112.24,3.81 TP70.1 ; TP70.1 113.67,2.38 ; TP70.1 113.67,5.24 ; TP70.1 115.09,3.81 ; 31.37,40.33 J29.3 ; J29.3 31.37,42.47 ; J29.3 32.44,41.4 ; J29.3 30.3,41.4 ; 119.92,58.64 J19.20 ; J19.20 121.04,57.86 ; J19.20 122.17,58.64 ; J19.20 121.04,59.42 ; 42.42,48.34 J27.15 ; J27.15 43.49,49.4 ; J27.15 42.42,50.47 ; J27.15 41.35,49.4 ; 2.31,30.2 J7.4 ; J7.4 0.93,31.57 ; J7.4 3.69,31.57 ; J7.4 2.31,32.95 ; J8.4 2.31,45.65 ; J8.4 2.31,42.9 ; J8.4 3.69,44.27 ; J8.4 0.93,44.27 ; J8.1 10.69,44.27 ; J8.1 9.31,42.9 ; J8.1 9.31,45.65 ; J8.1 7.93,44.27 ; J9.3 2.31,52.35 ; J9.3 0.93,50.98 ; J9.3 3.69,50.98 ; J9.3 2.31,49.6 ; J26.21 62.37,65.02 ; J26.21 62.37,62.77 ; J26.21 61.6,63.89 ; J26.21 63.15,63.89 ; 113.62,62.48 J28.7 114.3,61.81 ; 9.31,24.2 J7.2 ; J7.2 7.93,25.58 ; J7.2 10.69,25.58 ; J7.2 9.31,26.95 ; J26.20 52.3,63.89 ; J26.20 51.52,62.77 ; J26.20 51.52,65.02 ; J26.20 50.75,63.89 ; 2.31,17.5 J6.4 ; J6.4 2.31,20.25 ; J6.4 3.69,18.87 ; J6.4 0.93,18.87 ; J9.2 10.69,50.98 ; J9.2 9.31,49.6 ; J9.2 7.93,50.98 ; J9.2 9.31,52.35 ; J26.22 52.3,68.39 ; J26.22 51.52,67.37 ; J26.22 50.75,68.39 ; J6.1 10.69,18.87 ; J6.1 7.93,18.87 ; J6.1 9.31,17.5 ; J6.1 9.31,20.25 ; 124.52,47.79 J19.23 ; J19.23 125.54,48.57 ; J19.23 125.54,47.01 ; 25.04,34.86 TP2.1 ; TP2.1 25.55,35.37 ; TP2.1 26.06,34.86 ; TP2.1 25.55,34.35
  GND3 w0.254: J19.21 121.04,48.57 ; J19.21 119.92,47.79 ; J19.21 121.04,47.01 ; J19.21 122.17,47.79 ; J9.4 3.69,56.97 ; J9.4 2.31,58.35 ; J9.4 2.31,55.6 ; J9.4 0.93,56.97 ; J19.23 125.54,48.57 ; J19.23 124.52,47.79 ; J19.23 125.54,47.01 ; 122.45,12.5 J25.2 ; J25.2 123.28,10.57 ; J25.2 124.1,12.5 ; J25.2 123.28,14.43 ; 7.93,56.97 J9.1 ; J9.1 9.31,55.6 ; J9.1 9.31,58.35 ; J9.1 10.69,56.97 ; 7.93,44.27 J8.1 ; J8.1 10.69,44.27 ; J8.1 9.31,45.65 ; J8.1 9.31,42.9 ; J6.1 10.69,18.87 ; J6.1 7.93,18.87 ; J6.1 9.31,20.25 ; J6.1 9.31,17.5 ; 2.31,30.2 J7.4 ; J7.4 0.93,31.57 ; J7.4 2.31,32.95 ; J7.4 3.69,31.57 ; J8.2 9.31,39.65 ; J8.2 7.93,38.28 ; J8.2 10.69,38.28 ; J8.2 9.31,36.9 ; 25.55,34.35 TP2.1 ; TP2.1 26.06,34.86 ; TP2.1 25.55,35.37 ; TP2.1 25.04,34.86 ; J9.2 9.31,52.35 ; J9.2 10.69,50.98 ; J9.2 7.93,50.98 ; J9.2 9.31,49.6 ; 113.62,62.48 J28.7 114.3,61.81 ; 9.31,24.2 J7.2 ; J7.2 9.31,26.95 ; J7.2 10.69,25.58 ; J7.2 7.93,25.58 ; J27.15 42.42,50.47 ; J27.15 43.49,49.4 ; J27.15 41.35,49.4 ; J27.15 42.42,48.34 ; TP70.1 113.67,5.24 ; TP70.1 115.09,3.81 ; TP70.1 113.67,2.38 ; TP70.1 112.24,3.81 ; J26.21 63.15,63.89 ; J26.21 62.37,62.77 ; J26.21 61.6,63.89 ; J26.21 62.37,65.02 ; J29.3 32.44,41.4 ; J29.3 31.37,42.47 ; J29.3 30.3,41.4 ; J29.3 31.37,40.33 ; J9.3 3.69,50.98 ; J9.3 0.93,50.98 ; J9.3 2.31,52.35 ; J9.3 2.31,49.6 ; 2.31,36.9 J8.3 ; J8.3 0.93,38.28 ; J8.3 3.69,38.28 ; J8.3 2.31,39.65 ; 9.31,30.2 J7.1 ; J7.1 9.31,32.95 ; J7.1 10.69,31.57 ; J7.1 7.93,31.57 ; 61.6,68.39 J26.23 ; J26.23 62.37,67.37 ; J26.23 63.15,68.39 ; 2.31,42.9 J8.4 ; J8.4 3.69,44.27 ; J8.4 2.31,45.65 ; J8.4 0.93,44.27 ; TP72.1 3.33,8.06 ; TP72.1 1.91,9.49 ; TP72.1 1.91,6.64 ; J25.3 120.47,18.13 ; J25.3 118.55,17.3 ; J25.3 120.47,16.47 ; J25.3 122.4,17.3 ; J26.22 52.3,68.39 ; J26.22 51.52,67.37 ; J26.22 50.75,68.39 ; J6.4 2.31,20.25 ; J6.4 0.93,18.87 ; J6.4 2.31,17.5 ; J6.4 3.69,18.87 ; 0.93,25.58 J7.3 ; J7.3 3.69,25.58 ; J7.3 2.31,24.2 ; J7.3 2.31,26.95 ; 119.92,58.64 J19.20 ; J19.20 122.17,58.64 ; J19.20 121.04,59.42 ; J19.20 121.04,57.86 ; J6.3 2.31,14.25 ; J6.3 2.31,11.5 ; J6.3 0.93,12.88 ; J6.3 3.69,12.88 ; 7.93,12.88 J6.2 ; J6.2 9.31,11.5 ; J6.2 9.31,14.25 ; J6.2 10.69,12.88 ; 113.62,63.75 J28.5 113.77,63.22 ; J26.20 52.3,63.89 ; J26.20 51.52,62.77 ; J26.20 51.52,65.02 ; J26.20 50.75,63.89 ; 39.88,48.34 J27.16 ; J27.16 39.88,50.47 ; J27.16 40.95,49.4 ; J27.16 38.81,49.4 ; 125.54,57.86 J19.22 ; J19.22 124.52,58.64 ; J19.22 125.54,59.42
  INNER2 w0.254: 121.04,47.01 J19.21 ; J19.21 121.04,48.57 ; J19.21 122.17,47.79 ; J19.21 119.92,47.79 ; 125.54,47.01 J19.23 ; J19.23 125.54,48.57 ; J19.23 124.52,47.79 ; 119.92,58.64 J19.20 ; J19.20 121.04,59.42 ; J19.20 121.04,57.86 ; J19.20 122.17,58.64 ; 124.52,58.64 J19.22 ; J19.22 125.54,57.86 ; J19.22 125.54,59.42
  INNER2 w0.381: J7.4 3.33,30.55 ; J7.4 1.28,30.55 ; J7.4 1.28,32.6 ; J7.4 3.33,32.6 ; J8.3 3.33,39.3 ; J8.3 1.28,37.25 ; J8.3 1.28,39.3 ; J8.3 3.33,37.25 ; 113.77,63.22 J28.5 113.77,64.28 ; 25.14,34.45 TP2.1 ; TP2.1 25.96,35.27 ; TP2.1 25.14,35.27 ; TP2.1 25.96,34.45 ; 1.28,49.95 J9.3 ; J9.3 1.28,52 ; J9.3 3.33,52 ; J9.3 3.33,49.95 ; J9.2 10.33,49.95 ; J9.2 8.28,52 ; J9.2 8.28,49.95 ; J9.2 10.33,52 ; J6.1 10.33,19.9 ; J6.1 8.28,19.9 ; J6.1 10.33,17.85 ; J6.1 8.28,17.85 ; J7.1 10.33,30.55 ; J7.1 8.28,32.6 ; J7.1 8.28,30.55 ; J7.1 10.33,32.6 ; 122.56,10.57 J25.2 ; J25.2 123.99,10.57 ; J25.2 122.56,14.43 ; J25.2 123.99,14.43 ; J28.7 114.83,61.95 ; J28.7 113.77,61.95 ; J28.7 113.77,63.01 ; 8.28,11.85 J6.2 ; J6.2 10.33,11.85 ; J6.2 8.28,13.9 ; J6.2 10.33,13.9 ; 1.28,19.9 J6.4 ; J6.4 3.33,19.9 ; J6.4 3.33,17.85 ; J6.4 1.28,17.85 ; J8.4 3.33,43.25 ; J8.4 1.28,43.25 ; J8.4 1.28,45.3 ; J8.4 3.33,45.3 ; J9.1 10.33,58 ; J9.1 8.28,55.95 ; J9.1 10.33,55.95 ; J9.1 8.28,58 ; 8.28,26.6 J7.2 ; J7.2 8.28,24.55 ; J7.2 10.33,26.6 ; J7.2 10.33,24.55 ; J6.3 3.33,11.85 ; J6.3 1.28,11.85 ; J6.3 1.28,13.9 ; J6.3 3.33,13.9 ; J7.3 3.33,26.6 ; J7.3 1.28,26.6 ; J7.3 3.33,24.55 ; J7.3 1.28,24.55 ; J8.1 10.33,45.3 ; J8.1 10.33,43.25 ; J8.1 8.28,45.3 ; J8.1 8.28,43.25 ; J9.4 3.33,55.95 ; J9.4 1.28,55.95 ; J9.4 1.28,58 ; J9.4 3.33,58 ; 118.55,18.01 J25.3 ; J25.3 122.4,16.58 ; J25.3 122.4,18.01 ; J25.3 118.55,16.58 ; 8.28,39.3 J8.2 ; J8.2 10.33,39.3 ; J8.2 10.33,37.25 ; J8.2 8.28,37.25 ; 0.84,7 TP72.1 ; TP72.1 0.84,9.13 ; TP72.1 2.97,9.13 ; TP72.1 2.97,7 ; 112.6,2.75 TP70.1 ; TP70.1 114.73,4.87 ; TP70.1 114.73,2.75 ; TP70.1 112.6,4.87
  GND4 w0.254: J27.15 42.42,50.47 ; J27.15 43.49,49.4 ; J27.15 41.35,49.4 ; J27.15 42.42,48.34 ; J8.3 3.69,38.28 ; J8.3 2.31,39.65 ; J8.3 0.93,38.28 ; J8.3 2.31,36.9 ; 0.93,56.97 J9.4 ; J9.4 3.69,56.97 ; J9.4 2.31,58.35 ; J9.4 2.31,55.6 ; 7.93,50.98 J9.2 ; J9.2 9.31,52.35 ; J9.2 10.69,50.98 ; J9.2 9.31,49.6 ; 7.93,56.97 J9.1 ; J9.1 10.69,56.97 ; J9.1 9.31,58.35 ; J9.1 9.31,55.6 ; 7.93,18.87 J6.1 ; J6.1 9.31,20.25 ; J6.1 10.69,18.87 ; J6.1 9.31,17.5 ; 30.3,41.4 J29.3 ; J29.3 31.37,40.33 ; J29.3 31.37,42.47 ; J29.3 32.44,41.4 ; TP72.1 1.91,9.49 ; TP72.1 1.91,6.64 ; TP72.1 3.33,8.06 ; J6.3 3.69,12.88 ; J6.3 0.93,12.88 ; J6.3 2.31,14.25 ; J6.3 2.31,11.5 ; 123.28,10.57 J25.2 ; J25.2 122.45,12.5 ; J25.2 123.28,14.43 ; J25.2 124.1,12.5 ; J6.2 9.31,14.25 ; J6.2 7.93,12.88 ; J6.2 9.31,11.5 ; J6.2 10.69,12.88 ; 2.31,49.6 J9.3 ; J9.3 3.69,50.98 ; J9.3 0.93,50.98 ; J9.3 2.31,52.35 ; 120.47,16.47 J25.3 ; J25.3 122.4,17.3 ; J25.3 120.47,18.13 ; J25.3 118.55,17.3 ; 2.31,30.2 J7.4 ; J7.4 3.69,31.57 ; J7.4 2.31,32.95 ; J7.4 0.93,31.57 ; J19.22 125.54,59.42 ; J19.22 124.52,58.64 ; J19.22 125.54,57.86 ; 50.75,68.39 J26.22 ; J26.22 51.52,67.37 ; J26.22 52.3,68.39 ; J7.1 10.69,31.57 ; J7.1 9.31,30.2 ; J7.1 7.93,31.57 ; J7.1 9.31,32.95 ; J6.4 3.69,18.87 ; J6.4 0.93,18.87 ; J6.4 2.31,17.5 ; J6.4 2.31,20.25 ; TP70.1 115.09,3.81 ; TP70.1 113.67,5.24 ; TP70.1 112.24,3.81 ; TP70.1 113.67,2.38 ; 7.93,25.58 J7.2 ; J7.2 10.69,25.58 ; J7.2 9.31,24.2 ; J7.2 9.31,26.95 ; J8.4 2.31,45.65 ; J8.4 3.69,44.27 ; J8.4 2.31,42.9 ; J8.4 0.93,44.27 ; J26.20 51.52,65.02 ; J26.20 51.52,62.77 ; J26.20 52.3,63.89 ; J26.20 50.75,63.89 ; TP2.1 26.06,34.86 ; TP2.1 25.04,34.86 ; TP2.1 25.55,35.37 ; TP2.1 25.55,34.35 ; 121.04,57.86 J19.20 ; J19.20 121.04,59.42 ; J19.20 122.17,58.64 ; J19.20 119.92,58.64 ; J8.2 10.69,38.28 ; J8.2 9.31,36.9 ; J8.2 7.93,38.28 ; J8.2 9.31,39.65 ; J27.16 39.88,50.47 ; J27.16 38.81,49.4 ; J27.16 40.95,49.4 ; J27.16 39.88,48.34 ; J26.21 63.15,63.89 ; J26.21 61.6,63.89 ; J26.21 62.37,65.02 ; J26.21 62.37,62.77 ; 113.62,62.48 J28.7 114.3,61.81 ; 119.92,47.79 J19.21 ; J19.21 122.17,47.79 ; J19.21 121.04,47.01 ; J19.21 121.04,48.57 ; 113.77,63.22 J28.5 113.62,63.75 ; 61.6,68.39 J26.23 ; J26.23 63.15,68.39 ; J26.23 62.37,67.37 ; J8.1 9.31,45.65 ; J8.1 7.93,44.27 ; J8.1 10.69,44.27 ; J8.1 9.31,42.9 ; 125.54,47.01 J19.23 ; J19.23 125.54,48.57 ; J19.23 124.52,47.79 ; J7.3 3.69,25.58 ; J7.3 0.93,25.58 ; J7.3 2.31,26.95 ; J7.3 2.31,24.2
  BOTTOM w0.203: v1(27.48,63.2) 27.63,63.2 28,62.83 U49.4
  BOTTOM w0.254: v1(36.07,51.24) 35.79,50.97 U38.15 ; U46.10 v1(72.01,55.98) ; v1(16.76,65.23) R240.2 v1(16.76,66.8) ; U46.14 v1(72.01,53.38) ; U38.2 35.79,46.44 v1(36.07,46.16) ; U38.14 v1(35.29,51.24) ; U46.11 v1(72.01,55.33) ; U46.13 v1(72.01,54.03)
  BOTTOM w0.279: J13.58 v1(50.39,27.58) ; U28.2 v1(40.2,41.4) ; J13.57 v1(50.39,24.94) ; J13.16 v1(60.89,30.63)
  BOTTOM w0.305: v1(97.41,4.7) R324.2 96.52,3.18 R323.2 ; v1(114.3,58.67) 114.61,58.99 C166.2 C176.2 114.94,57.66 v1(114.3,57.66) ; U42.2 v1(118.55,58.04) ; v2(119.63,45.91) 119.38,46.16 R315.2
  BOTTOM w0.381: v1(28.88,19.96) 28.88,19.43 C51.1 ; C140.2 95.5,41.4 v1(95.36,41.54) ; R290.2 64.77,41.91 v1(64.77,42.67) ; R61.2 38.97,17.02 v1(39.93,17.97) ; C81.1 v2(20.65,37.95) C79.1 ; C109.2 98.42,66.11 v1(98.3,66.23) ; R296.2 v1(116.71,68.28) ; Q8.2 98.86,8.39 v2(98.42,8.83) ; R195.2 26.16,9.65 26.44,9.93 v2(26.89,9.93) ; C65.1 v2(20.65,12.55) C67.1 ; R112.1 59.74,21.08 v1(59.74,21.68) ; R28.2 17.27,57.77 v2(17.27,57.09) ; Q7.2 98.05,4.06 v1(97.41,4.7) ; C110.2 v1(103.06,62.93) ; J13.61 J13.62 ; v1(124.78,61.09) 124.08,61.09 R295.2 ; C71.1 v2(20.65,25.25) C69.1 ; v2(81.53,6.73) 80.9,6.73 R201.2 ; C111.2 v1(111.82,65.6) ; v1(47.22,26.26) J13.64 J13.63 57.18,26.26 v1(59.82,26.26) ; v1(36.82,4.83) C184.2 C182.2 ; C194.2 v1(28.95,60.64) ; C222.2 v1(48.77,51.69) ; C180.2 v1(22.86,2.02) ; v1(29.81,54.76) C191.2 ; v1(52.5,57.66) 52.07,57.66 C221.2 ; R298.2 v1(112.01,61.09) ; U46.8 v1(66.17,56.63) ; v1(33.12,17.02) C63.2 R53.2 ; R193.2 v1(26.16,1.71) ; C85.1 v2(20.65,50.66) C83.1 ; C183.2 v1(36.82,8.32) ; R31.2 v1(24.2,58.99) ; C220.2 58.67,63.23 v1(58.15,63.75) ; v1(53.5,53.85) 53.28,53.63 C223.2 ; v1(110.37,59.81) C175.2 C177.2 110.55,57.66 v1(111.12,57.66) ; R203.2 v1(12.06,1.91) ; U7.2 v1(32.37,37.85) ; R207.2 v1(83.57,14.16) ; R166.2 v1(100.52,65.79) ; R181.2 v1(89.72,25.34) ; R297.2 v1(113.16,61.09) ; v1(122.75,60.07) C217.2 ; v1(70.87,61.02) C264.2
  BOTTOM w0.508: C86.2 v2(21.82,44.93) ; R183.2 v2(99.57,23.37) ; C70.2 v2(19.51,19.53) ; v2(82.89,69.04) 82.89,68.03 C168.2 ; C80.2 v2(19.51,32.23) ; C72.2 v2(21.82,19.53) ; C150.2 v2(102.11,23.37) ; C152.2 v2(104.65,42.16) ; R182.2 v2(99.57,42.16) ; C84.2 v2(19.51,44.93) ; v2(20.89,6.79) 21.21,7.11 21.21,7.36 21.72,7.87 C68.2 ; C153.2 v2(102.11,42.16) ; C151.2 v2(104.65,23.37) ; C82.2 v2(21.82,32.23) ; C66.2 v2(19.51,6.83)
  BOTTOM w0.711: 112.66,2.8 TP70.1 ; TP70.1 114.67,4.82 ; TP70.1 114.67,2.8 ; TP70.1 112.66,4.82
  vias: v1(19.61,63.6) v1(26.54,59.44) v1(26.54,56.9) v1(28.69,36) v1(28.69,35.18) v1(30.86,60.71) v1(31.75,49.34) v1(31.75,48.07) v1(31.88,57.66) v1(31.88,56.64) v1(32.89,60.71) v1(32.89,57.66) v1(32.89,56.64) v1(33.66,48.7) v1(37.26,15.62) v1(37.26,14.99) v1(37.26,14.35) v1(37.26,13.72) v1(39.93,20.07) v1(39.93,18.99) v1(41.73,29.79) v1(41.73,28.68) v1(43.23,29.4) v1(43.23,27.37) v1(51.31,46.61) v1(51.31,45.47) v1(51.31,44.32) v1(51.31,43.18) v1(51.31,42.04) v1(51.44,38.99) v1(51.94,47.37) v1(52.45,38.99) v1(52.96,47.37) v1(53.09,40.01) v1(53.47,45.21) v1(53.47,43.18) v1(53.47,41.15) v1(53.98,47.37) v1(54.1,40.01) v1(54.48,44.2) v1(54.48,42.16) v1(54.99,47.37) v1(55.12,38.99) v1(55.5,45.21) v1(55.5,43.18) v1(55.5,41.15) v1(55.75,46.23) v1(56.13,38.99) v1(56.52,44.2) v1(56.52,42.16) v1(56.77,46.23) v1(57.15,38.99) v1(57.53,47.37) v1(57.53,45.21) v1(57.53,43.18) v1(57.53,41.15) v1(58.17,38.99) v1(58.42,47.37) v1(58.42,46.23) v1(58.55,40.01) v1(59.69,45.47) v1(59.69,44.45) v1(59.69,43.43) v1(59.69,42.42) v1(59.69,41.4) v1(59.69,40.39) v1(81.22,18.8) v1(81.22,17.78) v1(82.61,18.8) v1(82.61,17.78) v1(84.2,36.07) v1(84.2,34.8) v1(85.22,34.8) v1(89.03,35.18) v1(89.03,33.4) v1(89.03,31.62) v1(89.92,34.29) v1(89.92,32.51) v1(90.81,35.18) v1(90.81,33.4) v1(90.81,31.62) v1(91.69,34.29) v1(91.69,32.51) v1(92.27,21.02) v1(92.27,20.13) v1(92.58,35.18) v1(92.58,33.4) v1(92.58,31.62) v1(92.71,0.89) v1(93.98,53.21) v1(93.98,49.66) v1(94.36,38.61) v1(94.61,0.89) v1(95.25,38.61) v1(95.76,53.21) v1(95.76,51.44) v1(95.76,49.66) v1(95.76,47.88) v1(95.89,54.99) v1(96.39,5.71) v1(96.39,4.7) v1(96.52,0.89) v1(97.41,5.71) v1(97.54,54.99) v1(97.54,53.21) v1(97.54,51.44) v1(97.54,49.66) v1(97.54,47.88) v1(97.89,36.77) v1(97.89,31.01) v1(97.92,29.54) v1(98.17,34.54) v1(98.17,33.22) v1(98.42,0.89) v1(99.31,54.99) v1(99.31,53.21) v1(99.31,51.44) v1(99.31,49.66) v1(99.31,47.88) v1(100.33,0.89) v1(101.09,53.21) v1(102.23,0.89) v1(104.14,0.89) v1(106.05,0.89) v1(107.95,18.67) v1(107.95,17.59) v1(107.95,16.51) v1(107.95,0.89) v1(108.84,18.67) v1(108.84,17.59) v1(108.84,16.51) v1(109.73,18.67) v1(109.73,17.59) v1(109.73,16.51) v1(109.86,0.89) v1(111.76,0.89) v1(113.03,47.56) v1(113.03,46.67) v1(113.67,0.89) v1(115.57,0.89) v1(117.47,0.89) v1(119.38,0.89) v2(4.7,61.4) v2(4.7,60.33) v2(7.11,0.89) v2(8.26,0.89) v2(17.27,61.53) v2(18.41,61.53) v2(18.41,57.09) v2(19.56,61.53) v2(19.56,57.09) v2(20.7,61.53) v2(20.7,57.09) v2(21.84,61.53) v2(21.84,57.09) v2(25.59,12.83) v2(26.61,12.83) v2(36.13,66.55) v2(36.13,65.53) v2(76.07,68.07) v2(76.07,66.93) v2(87.82,16.38) v2(88.46,23.88) v2(88.46,22.61) v2(88.77,62.99) v2(88.84,16.38) v2(89.73,62.99) v2(89.79,23.88) v2(91.5,18.86) v2(98.42,11.11) v2(98.42,9.97) v2(99.57,11.11) v2(99.57,9.97) v2(99.57,8.83) v2(100.71,9.97) v2(100.71,8.83) v2(100.97,21.59) v2(102.23,21.59) v2(103.5,21.59) v2(104.78,21.59) v2(106.05,21.59) v2(107.31,21.59) v2(108.2,20.45) v2(108.58,21.59) v2(108.84,10.67) v2(109.47,20.45) v2(109.86,21.59) v2(109.98,11.81) v2(109.98,10.67) v2(111.12,21.59) v2(111.12,11.81) v2(111.12,10.67) v2(112.27,10.67) v2(112.27,9.53) v2(112.27,8.38) v2(112.39,21.59) v2(113.03,48.39) v2(113.41,45.93) v2(113.41,10.67) v2(113.41,9.53) v2(113.41,8.38) v2(113.41,7.24) v2(113.41,6.1) v2(113.67,21.59) v2(114.55,10.67) v2(114.55,9.53) v2(114.55,8.38) v2(114.55,7.24) v2(114.55,6.1) v2(114.68,20.7) v2(114.68,19.43) v2(114.68,18.16) v2(114.81,45.91) v2(115.57,44.07) v2(116.71,44.07) v2(118.68,67.88) v2(119.57,67.88) v2(119.63,44.96) v2(121.41,8.51) v2(121.41,7.49) v2(121.54,45.91) v2(122.49,45.91) v2(123.44,45.91) v2(123.44,44.96) v2(124.4,45.91) v2(124.4,44.96)
DVDD_HDMI_IN: length 7.3
  TOP w0.305: U44.40 v1(55.25,36.32) ; v1(48.51,43.31) 48.64,43.43 U44.24 ; U44.60 v1(62.36,44.93) ; U44.52 v1(62.36,40.93)
  BOTTOM w0.381: v1(62.36,44.93) 61.62,44.93 C239.1 ; v1(55.25,36.32) 55.25,37.08 C242.1 ; C241.1 49.27,43.31 v1(48.51,43.31)
  vias: v1(62.29,38.93)
PVDD_HDMI_IN: length 1.2
  TOP w0.305: U44.57 v1(62.36,43.43)
VDD1P1: length 4.1
  TOP w0.203: v1(90.68,28.83) 90.55,28.96 90.55,29.92 U9.42 ; U9.31 86.57,33.13 v1(86.36,32.92) ; v1(88.05,37.72) 88.05,36.83 U9.24 ; v1(95.25,33.13) U9.6
  vias: v1(87,37.72) v1(89.28,37.72)
VDD18_P: length 22
  TOP w0.508: C50.2 29.8,20.04 v1(29.72,19.96) v1(30.41,19.96) 31.61,21.17 31.61,23.94 32.08,24.41 C47.1 32.08,28.74 30.66,30.16 30.31,30.16 v1(29.9,30.57)
  TOP w0.635: L8.2 29.84,33.48 C49.2 C48.1 29.84,30.63 v1(29.9,30.57)
  BOTTOM w0.279: 30.41,20.38 v1(30.41,19.96) ; v1(29.72,19.96) 29.9,20.15 29.9,20.57
  BOTTOM w0.292: U6.48 29.9,20.57 ; U6.1 v1(29.9,30.57) 30.16,30.57 30.41,30.33 U6.2 ; U6.47 30.41,20.38
  BOTTOM w0.381: C51.2 30.41,19.43 v1(30.41,19.96)
VDD18A: length 5
  TOP w0.508: L4.2 38.16,16.65 C27.1 C28.1 C29.2 38.11,20.25 v1(38.11,21.04)
  BOTTOM w0.292: U6.32 v1(38.11,21.04)
VDD_1V1: length 9.9
  TOP w0.203: U5.16 96.15,6.97 95.38,7.75
  TOP w0.381: R33.1 94.13,3.89 v1(93.46,4.57)
  PWR2 w0.254: 92.92,9.22 TP13.1 ; TP13.1 93.77,9.22 ; TP13.1 92.92,10.08 ; TP13.1 93.77,10.08
  BOTTOM w0.381: R34.2 v1(94.49,10.67) ; v1(93.46,4.57) 93.46,8.52 v1(93.34,8.64)
  vias: v1(26.47,19.49) v1(26.47,18.8) v1(35.55,19.49) v1(36.37,19.49) v1(39.87,27.24) v1(40.56,27.24) v1(41.26,27.24) v1(86.49,40.7) v1(86.49,40.01) v1(88.27,40.7) v1(88.27,40.01) v1(93.34,10.67) v1(94.49,9.65) v1(94.49,8.64)
VDD_1V1_EN: length 7.6
  TOP w0.203: U5.13 97.74,6.79 v1(98.04,6.79)
  BOTTOM w0.203: R172.2 TP32.1 97.41,12.06 97.41,7.43 v1(98.04,6.79)
VDD_1V8: length 3.6
  TOP w0.254: TP74.1 35.4,16.3 ; TP74.1 34.55,15.45 ; TP74.1 34.55,16.3 ; TP74.1 35.4,15.45
  BOTTOM w0.254: 34.55,15.45 TP74.1 35.4,15.45
  vias: v1(34.98,4.89) v1(35.74,4.89) v1(36.12,16.32) v1(36.12,15.62)
VDD_2V5: length 6.8
  TOP w0.203: v1(94.17,19.94) 93.79,20.32 U13.6
  TOP w0.381: v1(94.17,19.94) 94.55,19.56 R120.1
  BOTTOM w0.381: R118.2 93.31,24.89 v1(94.17,24.89) ; v1(94.17,23.88) v1(94.17,19.94)
  vias: v1(94.81,26.54) v1(95.76,26.54) v1(96.71,26.54)
VDD_2V5_EN: length 4.7
  TOP w0.203: U13.3 90.8,20.32 90.49,20.02 90.49,19.62 v1(90.23,19.37)
  BOTTOM w0.203: v1(90.23,19.37) 89.66,18.8 R309.2 88.58,18.8 TP33.1
VDD_3V3: length 81.8
  TOP w0.203: U16.1 v1(93.75,44.45) ; J21.4 v2(80.69,69.04)
  TOP w0.254: U16.12 v1(99.25,44.45) ; U48.20 v1(78.74,19.04)
  TOP w0.292: U16.33 v1(101.25,58.42)
  TOP w0.305: R108.1 62.13,30.87 v1(61.89,30.63) ; U41.5 v1(120.84,61.09) ; R312.1 v1(106.8,58.67)
  TOP w0.381: v1(83.19,12.38) R200.1 R202.1 ; R138.1 v1(97.72,42.42) ; R107.1 61.55,25.6 v1(60.91,25.6) ; R137.1 v1(102.46,59.28) ; v1(72.01,52.08) 71.26,52.08 C265.1 ; R190.1 15.68,7.56 14.35,6.22 v1(14.35,5.97) ; R237.1 78.74,21.34 v1(78.74,20.19) ; v1(44.45,66.42) C263.1 v1(44.45,67.94) ; C218.1 118.55,61.03 v1(118.55,61.98) ; v1(18.67,5.97) 18.35,6.29 R192.1 ; v1(37.34,47.95) 36.46,47.95 C207.1 ; v1(12.57,5.97) 12.57,6.48 13.02,6.92 R188.1 ; R184.1 v1(34.28,12.44) ; R133.1 v1(103.25,44.13) ; U10.5 v1(101.35,63.69) ; v1(10.35,5.97) R185.1 ; R222.2 v1(40.45,42.55) ; U22.24 v2(20.95,2.77) ; C181.1 v1(43.12,41.4)
  PWR1 w0.254: TP83.1 20.24,2.75 ; TP83.1 18.12,2.75 ; TP83.1 20.24,4.87 ; TP83.1 18.12,4.87 ; J27.1 43.22,66.38 ; J27.1 43.22,67.99 ; J27.1 41.61,66.38 ; J27.1 41.61,67.99
  BOTTOM w0.254: U38.1 v1(37.34,47.95) ; U38.3 v1(35.29,46.16)
  BOTTOM w0.279: J13.1 v1(64.39,21.89) ; U28.5 v1(43.12,41.4) ; J13.12 v1(61.89,30.63)
  BOTTOM w0.305: U42.5 v1(118.55,61.98)
  BOTTOM w0.381: R205.1 v1(78.8,15.75) ; v1(78.74,19.04) 79.49,19.04 C187.1 ; R259.1 v1(102.49,2.92) ; v1(99.25,44.45) 99.25,45.27 C160.1 ; R316.1 R317.1 ; R317.1 110.64,50.14 R310.1 v1(112.78,50.14) ; R317.1 R318.1 111.51,51.31 v1(111.76,51.05) ; R155.1 77.72,56.13 78.49,55.37 79.25,55.37 80.01,56.13 R156.1 80.58,56.77 81.15,57.34 v1(81.15,57.91) ; C180.1 21.84,2.77 v2(20.95,2.77) ; R206.1 82.23,16.57 v1(83.25,15.56) ; R197.1 v1(31.75,1.71) ; R152.1 v1(69.72,62.04) ; v1(29.46,9.91) 28.7,9.15 R196.1 ; C217.1 121.79,61.09 v1(120.84,61.09) ; R132.1 102.62,44.13 v1(103.25,44.13) ; R154.1 v1(74.3,62.04) ; R194.1 v1(27.69,1.71) ; R158.1 v1(92.9,56.83) ; R157.1 v1(75.44,56.07) ; R153.1 v1(72.01,62.04) ; R260.1 v1(105.6,2.92) ; U46.16 v1(72.01,52.08) ; C110.1 101.35,62.93 v1(101.35,63.69) ; R204.1 v1(12.06,3.17) ; C186.1 v1(78.74,20.19) ; R308.1 v1(12.06,4.45) ; R172.1 v1(98.55,14.61) ; R309.1 v1(87.82,17.78)
  BOTTOM w0.508: v1(35.74,8.32) v1(35.74,7.62) 35.8,7.56 C182.1
  vias: v1(44.37,32.58) v1(44.37,31.88) v1(48.01,37.27) v1(48.01,36.32) v1(49.02,37.27) v1(51.56,50.93) v1(52.45,50.93) v1(84.77,28.7) v1(84.77,27.94) v1(91.95,44.45) v1(92.84,44.45) v2(102.36,58.29) v2(103.5,58.29) v2(104.65,44.83) v2(106.68,44.83)
VDD_5V0: length 13.1
  TOP w0.279: v1(51.18,51.69) 51.5,52.01 U43.1
  TOP w0.305: U20.1 108.91,58.66 v1(108.58,58.99)
  TOP w0.381: U10.3 v1(98.3,64.96) ; R277.1 v1(63.44,56.26) ; R276.1 v1(63.44,57.4)
  INNER1 w0.254: TP12.1 118.66,47.67 ; TP12.1 117.81,47.67 ; TP12.1 118.66,46.82 ; TP12.1 117.81,46.82
  BOTTOM w0.305: R313.1 117.09,47.75 117.6,47.24 TP12.1 R314.1
  BOTTOM w0.381: C222.1 v1(51.18,51.69) ; v1(98.3,64.96) 98.42,65.09 C109.1 ; v1(108.58,58.99) C175.1
  vias: v2(100.84,61.59) v2(102.11,61.59) v2(103.38,61.59) v2(114.81,48.64) v2(114.81,47.43)
VDD_5V0_EN: length 10
  TOP w0.254: U4.4 v1(111.98,48.39)
  BOTTOM w0.203: v1(111.98,48.39) 111.98,49.11 R310.2 113.31,49.12 113.92,48.51 113.92,47.24 114.55,46.61 116.84,46.61 TP34.1
VDD_BB_1V8: length 7.4
  TOP w0.254: TP75.1 40.61,15.6 ; TP75.1 40.61,14.75 ; TP75.1 39.75,14.75 ; TP75.1 39.75,15.6
  TOP w0.305: U14.1 v1(96.21,42.35)
  TOP w0.381: v1(95.43,40.2) 96.01,40.2 U14.4
  PWR2 w0.254: 39.75,14.75 TP75.1 ; TP75.1 40.61,15.6 ; TP75.1 39.75,15.6 ; TP75.1 40.61,14.75
  BOTTOM w0.381: C140.1 95.62,40.38 v1(95.43,40.2)
  vias: v1(25.15,33.4) v1(25.13,32.7) v1(25.13,32) v1(31.99,34.23) v1(31.99,33.53) v1(39.23,15.56) v1(39.23,14.8) v1(59.94,37.66) v1(59.94,36.77) v1(61.53,48.51) v1(62.29,48.51) v1(65.53,47.5) v1(65.53,46.61) v1(87.38,42.29) v1(88.27,42.29)
VDD_BB_3V3: length 35.4
  TOP w0.305: U13.2 90.24,20.82
  TOP w0.381: R10.1 v1(101.09,16.97)
  TOP w0.508: 109.86,2.46 TP1.1 ; TP1.1 111.21,3.81 ; TP1.1 109.86,5.16 ; TP1.1 108.5,3.81
  INNER1 w0.381: TP1.1 110.92,4.87 ; TP1.1 108.79,2.75 ; TP1.1 108.79,4.87 ; TP1.1 110.92,2.75
  PWR2 w0.508: 108.43,3.81 TP1.1 ; TP1.1 109.86,2.38 ; TP1.1 109.86,5.24 ; TP1.1 111.28,3.81
  BOTTOM w0.381: v1(101.09,16.97) 102.22,15.84 102.22,11.82 v1(107.95,6.1) ; R8.1 v1(98.42,17.08)
  BOTTOM w0.508: C183.1 35.36,9.14 34.85,8.64 v1(34.85,8.32) v1(34.85,7.62)
  vias: v1(34.85,11.1) v1(35.61,11.07) v2(88.46,21.34) v2(88.46,20.07) v2(89.66,20.07) v2(104.52,5.08) v2(104.52,3.94) v2(105.66,5.08) v2(105.66,3.94) v2(106.81,5.08) v2(106.81,3.94) v2(107.95,5.08) v2(107.95,3.94) v2(109.22,44.7) v2(110.24,44.7) v2(111.25,45.97)
VDD_HDMI_5V0: length 13.6
  TOP w0.229: J19.18 v1(120.9,50.01)
  TOP w0.305: v1(116.84,58.86) 116.64,58.66 U20.38
  INNER1 w0.508: v1(120.9,50.01) 117.73,53.19 117.73,58.17 117.03,58.86 v1(116.84,58.86)
  BOTTOM w0.305: v1(116.84,58.86) 116.27,58.86 C166.1
VDD_SW_FPD: length 5
  TOP w0.508: v1(8,62.36) v1(8.89,62.36) 9.65,62.36 R250.1
  PWR1 w0.711: 4.11,62.02 TP11.1 4.11,59.65
  vias: v1(7.11,64.14) v1(7.11,63.25) v1(7.11,62.36) v1(8,64.14) v1(8,63.25) v1(8.89,64.14) v1(8.89,63.25) v1(9.78,64.14) v2(21.59,51.94) v2(21.59,39.24) v2(21.59,26.54) v2(21.59,13.84) v2(23.18,50.61) v2(23.18,48.96) v2(23.18,37.91) v2(23.18,36.26) v2(23.18,25.21) v2(23.18,23.56) v2(23.18,12.51) v2(23.18,10.86)
VDD_USB_3V3: length 5.8
  TOP w0.305: U47.6 30.67,58.86 v1(30.67,59.31) v1(30.67,60.01)
  TOP w0.381: v1(37.34,49.45) 36.46,49.45 C208.1 ; v1(30.67,59.31) 29.4,59.31 29.02,58.93 R301.1
  BOTTOM w0.254: U38.16 v1(37.34,49.45)
VDD_USB_5V0: length 5.1
  TOP w0.305: U47.8 v1(29.97,57.4) ; v1(29.97,58.36) 30.43,57.9 U47.7
  TOP w0.406: J23.1 v1(23.14,63.55)
  BOTTOM w0.203: U49.1 26.87,61.83 27.36,61.34 v1(27.36,61.2)
  vias: v1(28.57,56.64)
VDD_VIN: length 40.7
  TOP w0.381: 117.47,10.57 J25.1 ; J25.1 116.65,12.5 ; J25.1 117.47,14.43 ; J25.1 118.3,12.5 ; 117.73,2.46 TP27.1 117.73,5.16
  TOP w0.508: R249.1 25.17,62.56 24.28,62.56 24.08,62.36 v1(18.8,62.36) v1(17.91,62.36)
  PWR2 w0.711: TP27.1 119.16,3.81 ; TP27.1 117.73,5.24 ; TP27.1 117.73,2.38 ; TP27.1 116.3,3.81 ; 116.65,12.5 J25.1 ; J25.1 118.3,12.5 ; J25.1 117.47,10.57 ; J25.1 117.47,14.43
  BOTTOM w0.711: TP27.1 118.74,4.82 ; TP27.1 116.72,4.82 ; TP27.1 116.72,2.8 ; TP27.1 118.74,2.8 ; 116.76,10.57 J25.1 ; J25.1 118.19,14.43 ; J25.1 118.19,10.57 ; J25.1 116.76,14.43
  vias: v1(16,64.14) v1(17.02,64.14) v1(17.02,63.25) v1(17.02,62.36) v1(17.91,64.14) v1(17.91,63.25) v1(18.8,64.14) v1(18.8,63.25) v1(112.39,16.51) v1(113.41,16.51) v1(114.43,16.51) v1(114.43,14.22) v1(115.44,16.51) v1(115.44,14.22) v1(116.46,16.51) v1(116.46,15.49)
VDDA1P8: length 3.6
  TOP w0.279: U9.13 93.56,37.36 94.04,37.85 v1(94.81,37.85) ; U9.48 v1(93.56,28.32)
VDDA2P5: length 2
  TOP w0.203: v1(95.25,31.62) 94.26,31.62 U9.3 ; U9.9 v1(95.25,34.63)
VDDCSI: length 11.3
  TOP w0.508: v1(37.41,19.85) 36.63,20.62 C45.2 ; v1(37.41,27.1) 36.61,27.1 C43.1
  TOP w0.635: C45.2 C42.1 36.63,25.96 C44.2 ; L7.2 C44.2 ; C44.2 C43.1
  BOTTOM w0.292: U6.33 v1(37.41,19.85) ; U6.21 v1(37.41,27.1)
VDDFPD: length 10.3
  TOP w0.508: v1(28.27,23.1) 27.55,23.1 C55.2 ; C55.2 C54.1 C56.2 27.55,27.6 v1(28.27,27.6) ; C55.2 C53.1 27.55,21.99 L9.2
  BOTTOM w0.292: U6.61 v1(28.27,27.6) ; U6.52 v1(28.27,23.1)
VDDFPD18: length 16.2
  TOP w0.508: 29.19,26.1 29.18,26.11 C37.1 ; 29.19,26.1 C40.2 29.18,26.06 C39.2 ; 29.19,26.1 v1(28.3,26.1) ; v1(28.4,21.6) 28.4,21.82 C38.2 C39.2 ; C39.2 29.17,24.6 v1(28.28,24.6)
  TOP w0.635: L6.2 27.71,30.31 27.71,29.28 C36.1 27.54,29.1 v1(28.4,29.1) 29.15,29.1 C37.1
  BOTTOM w0.292: U6.64 v1(28.4,29.1) ; U6.49 v1(28.4,21.6) ; U6.55 v1(28.28,24.6) ; U6.58 v1(28.3,26.1)
